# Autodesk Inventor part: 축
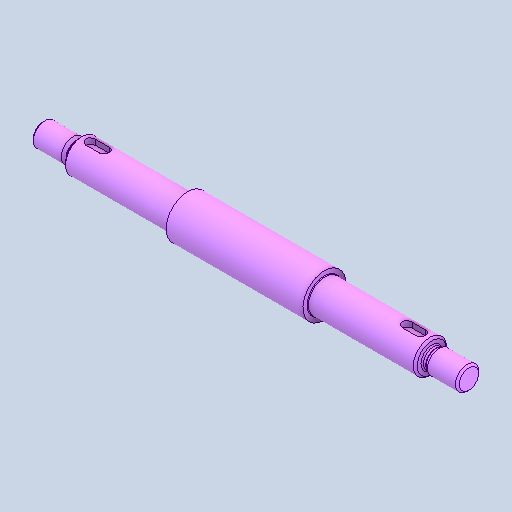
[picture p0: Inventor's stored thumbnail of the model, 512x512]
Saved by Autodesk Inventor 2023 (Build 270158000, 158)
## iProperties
Created: 2025-03
Part Number: 축
Material: 강철, 탄소
Document SubType Name: Modeling
Designer: User
Density: 7.85 g/cm^3
Appearance: 기본값
Author: jhkim
Sending System: Autodesk Inventor 2025
Preprocessor: ST-DEVELOPER v20
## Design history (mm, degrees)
feature "솔리드1"
node "솔리드2"
